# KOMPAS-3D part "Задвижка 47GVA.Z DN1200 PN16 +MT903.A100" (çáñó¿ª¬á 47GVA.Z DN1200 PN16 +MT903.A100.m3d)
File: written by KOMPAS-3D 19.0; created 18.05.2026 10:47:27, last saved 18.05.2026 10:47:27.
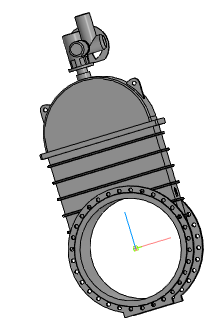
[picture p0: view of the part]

Document properties: Автор: Энергия; Полное имя файла: ..\Задвижка 47GVA.Z DN350_DN1200+MT903.A\Задвижка 47GVA.Z DN1200 PN16 +MT903.A100.a3d

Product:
- Part/product: Задвижка 47GVA.Z DN1200 PN16 +MT903.A100
    Масса: 6899.73
  - Body: Электропривод МТ903.А100 без блока управления
      Масса: 346.451
  - Body: Задвижка 47GVA.Z DN1200 PN16 без исполнит. мех.
      Масса: 6553.27

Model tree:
1. Операция без истории:1
2. Операция без истории:2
